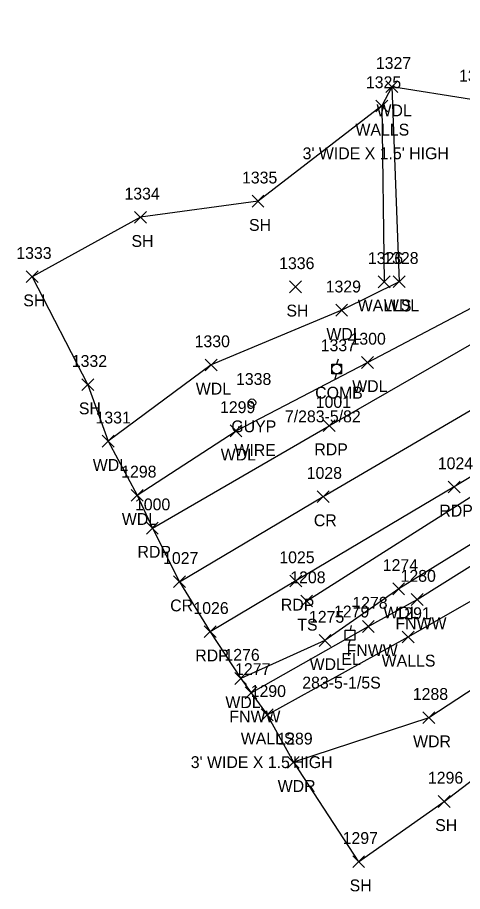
# Model space of a CAD drawing. Extents: x 1526508 to 1531550, y 369926 to 373082.
# Drawn here: x 1530637.1 to 1530712.1, y 369926.2 to 370073.8 of the extents above; entities that cross this region are included whole.
import ezdxf

# ---------------------------------------------------------------- set-up
doc = ezdxf.new("R2010")
doc.units = 0
for name, color, linetype in [('L_A', 7, 'Continuous'), ('L_C', 7, 'Continuous'), ('L_I', 7, 'Continuous'), ('L_TIC', 7, 'Continuous'), ('LAWA', 7, 'Continuous'), ('LELB', 7, 'Continuous'), ('LFNC', 7, 'Continuous'), ('LSOGP', 7, 'Continuous'), ('LWS', 7, 'Continuous'), ('P_A', 7, 'Continuous'), ('P_I', 7, 'Continuous'), ('P_TIC', 7, 'Continuous'), ('PET', 7, 'Continuous'), ('PRC', 7, 'Continuous'), ('U_A', 7, 'Continuous'), ('U_C', 7, 'Continuous'), ('U_I', 7, 'Continuous'), ('UEPT', 7, 'Continuous'), ('UP', 7, 'Continuous'), ('UPGW', 7, 'Continuous')]:
    doc.layers.add(name, color=color, linetype=linetype)

msp = doc.modelspace()

# ---------------------------------------------------------------- linework, layer by layer
at = {"layer": 'L_TIC'}
for points in [[(1530699.23, 370061.11), (1530701.23, 370063.11)], [(1530701.23, 370061.11), (1530699.23, 370063.11)], [(1530697.56, 370057.86), (1530699.56, 370059.86)], [(1530699.56, 370057.86), (1530697.56, 370059.86)], [(1530676.67, 370041.77), (1530678.67, 370043.77)], [(1530678.67, 370041.77), (1530676.67, 370043.77)], [(1530656.84, 370039.06), (1530658.84, 370041.06)], [(1530658.84, 370039.06), (1530656.84, 370041.06)], [(1530638.6, 370029.03), (1530640.6, 370031.03)], [(1530640.6, 370029.03), (1530638.6, 370031.03)], [(1530697.94, 370028.17), (1530699.94, 370030.17)], [(1530699.94, 370028.17), (1530697.94, 370030.17)], [(1530700.48, 370028.19), (1530702.48, 370030.19)], [(1530702.48, 370028.19), (1530700.48, 370030.19)], [(1530682.98, 370027.31), (1530684.98, 370029.31)], [(1530684.98, 370027.31), (1530682.98, 370029.31)], [(1530690.78, 370023.37), (1530692.78, 370025.37)], [(1530692.78, 370023.37), (1530690.78, 370025.37)], [(1530668.76, 370014.13), (1530670.76, 370016.13)], [(1530670.76, 370014.13), (1530668.76, 370016.13)], [(1530695.13, 370014.56), (1530697.13, 370016.56)], [(1530697.13, 370014.56), (1530695.13, 370016.56)], [(1530647.97, 370010.8), (1530649.97, 370012.8)], [(1530649.97, 370010.8), (1530647.97, 370012.8)], [(1530672.96, 370003), (1530674.96, 370005)], [(1530674.96, 370003), (1530672.96, 370005)], [(1530651.4, 370001.25), (1530653.4, 370003.25)], [(1530653.4, 370001.25), (1530651.4, 370003.25)], [(1530656.29, 369992.12), (1530658.29, 369994.12)], [(1530658.29, 369992.12), (1530656.29, 369994.12)], [(1530700.39, 369976.34), (1530702.39, 369978.34)], [(1530702.39, 369976.34), (1530700.39, 369978.34)], [(1530684.88, 369974.28), (1530686.88, 369976.28)], [(1530686.88, 369974.28), (1530684.88, 369976.28)], [(1530703.49, 369974.52), (1530705.49, 369976.52)], [(1530705.49, 369974.52), (1530703.49, 369976.52)], [(1530695.26, 369969.98), (1530697.26, 369971.98)], [(1530697.26, 369969.98), (1530695.26, 369971.98)], [(1530687.96, 369967.61), (1530689.96, 369969.61)], [(1530689.96, 369967.61), (1530687.96, 369969.61)], [(1530701.98, 369968.21), (1530703.98, 369970.21)], [(1530703.98, 369968.21), (1530701.98, 369970.21)], [(1530673.75, 369961.19), (1530675.75, 369963.19)], [(1530675.75, 369961.19), (1530673.75, 369963.19)], [(1530675.49, 369958.78), (1530677.49, 369960.78)], [(1530677.49, 369958.78), (1530675.49, 369960.78)], [(1530678.21, 369955.07), (1530680.21, 369957.07)], [(1530680.21, 369955.07), (1530678.21, 369957.07)], [(1530705.46, 369954.58), (1530707.46, 369956.58)], [(1530707.46, 369954.58), (1530705.46, 369956.58)], [(1530682.63, 369947.04), (1530684.63, 369949.04)], [(1530684.63, 369947.04), (1530682.63, 369949.04)], [(1530708.06, 369940.44), (1530710.06, 369942.44)], [(1530710.06, 369940.44), (1530708.06, 369942.44)], [(1530693.63, 369930.26), (1530695.63, 369932.26)], [(1530695.63, 369930.26), (1530693.63, 369932.26)]]:
    msp.add_lwpolyline(points, dxfattribs=at)
at = {"layer": 'LAWA'}
for points in [[(1530657.29, 369993.12), (1530673.96, 370004), (1530696.13, 370015.56), (1530718.14, 370027.13), (1530730.56, 370035.39), (1530739.6, 370038.43), (1530749.85, 370044.28), (1530746.24, 370053.12), (1530732.92, 370070.22)], [(1530700.23, 370062.11), (1530701.48, 370029.19), (1530691.78, 370024.37), (1530669.76, 370015.13), (1530652.4, 370002.25)], [(1530769.48, 370023.84), (1530754.36, 370014.7), (1530742.13, 370006.46), (1530732.58, 369998.98), (1530723.17, 369990.78), (1530701.39, 369977.34), (1530688.96, 369968.61), (1530674.75, 369962.19)], [(1530749.81, 369965.19), (1530736.04, 369980.46), (1530727.16, 369969.14), (1530706.46, 369955.58), (1530683.63, 369948.04)]]:
    msp.add_lwpolyline(points, dxfattribs=at)
at = {"layer": 'LELB'}
msp.add_lwpolyline([(1530685.88, 369975.28), (1530717.44, 369995.35), (1530750.55, 370015.24), (1530789.81, 370037.94), (1530822.42, 370057.69), (1530849.78, 370074.39), (1530878.97, 370089.95), (1530906.44, 370104.85), (1530934.55, 370113.45), (1530953.41, 370116.76)], dxfattribs=at)
at = {"layer": 'LFNC'}
msp.add_lwpolyline([(1530676.49, 369959.78), (1530696.26, 369970.98), (1530704.49, 369975.52), (1530724.71, 369988.17), (1530736.65, 369993.22), (1530745.64, 369985.38), (1530754.13, 369971.62)], dxfattribs=at)
at = {"layer": 'LSOGP'}
msp.add_lwpolyline([(1530713.68, 370059.96), (1530700.23, 370062.11), (1530698.56, 370058.86), (1530677.67, 370042.77), (1530657.84, 370040.06), (1530639.6, 370030.03), (1530648.97, 370011.8), (1530652.4, 370002.25), (1530657.29, 369993.12), (1530659.86, 369987.59), (1530664.43, 369978.53), (1530669.6, 369970.09), (1530674.75, 369962.19), (1530676.49, 369959.78), (1530679.21, 369956.07), (1530683.63, 369948.04), (1530694.63, 369931.26), (1530709.06, 369941.44), (1530721.94, 369951.28)], dxfattribs=at)
at = {"layer": 'LWS'}
for points in [[(1530698.56, 370058.86), (1530698.94, 370029.17)], [(1530679.21, 369956.07), (1530702.98, 369969.21), (1530717.25, 369977.41), (1530728.07, 369984.76)]]:
    msp.add_lwpolyline(points, dxfattribs=at)
at = {"layer": 'P_TIC'}
for points in [[(1530688.68, 370003.88), (1530690.68, 370005.88)], [(1530690.68, 370003.88), (1530688.68, 370005.88)], [(1530709.76, 369993.53), (1530711.76, 369995.53)], [(1530711.76, 369993.53), (1530709.76, 369995.53)], [(1530687.65, 369991.9), (1530689.65, 369993.9)], [(1530689.65, 369991.9), (1530687.65, 369993.9)], [(1530658.86, 369986.59), (1530660.86, 369988.59)], [(1530660.86, 369986.59), (1530658.86, 369988.59)], [(1530663.43, 369977.53), (1530665.43, 369979.53)], [(1530665.43, 369977.53), (1530663.43, 369979.53)], [(1530683.03, 369977.66), (1530685.03, 369979.66)], [(1530685.03, 369977.66), (1530683.03, 369979.66)], [(1530668.6, 369969.09), (1530670.6, 369971.09)], [(1530670.6, 369969.09), (1530668.6, 369971.09)]]:
    msp.add_lwpolyline(points, dxfattribs=at)
at = {"layer": 'PET'}
for points in [[(1530659.86, 369987.59), (1530689.68, 370004.88), (1530725.77, 370025.63), (1530760.95, 370046.59), (1530789.35, 370063.64), (1530821.52, 370083.59), (1530847.47, 370098.66), (1530877.57, 370115.25), (1530907.84, 370128.26), (1530938.81, 370136.76), (1530967.77, 370140.97), (1531005.44, 370146.08), (1531034.99, 370150.93)], [(1531038.44, 370130.38), (1531006.6, 370125.67), (1530965.47, 370120.56), (1530935.63, 370115.81), (1530906.91, 370106.24), (1530877.46, 370092.89), (1530855.5, 370080.74), (1530824.98, 370062.43), (1530800.48, 370048.15), (1530769.96, 370030.14), (1530741.1, 370012.79), (1530710.76, 369994.53), (1530684.03, 369978.66), (1530669.6, 369970.09)]]:
    msp.add_lwpolyline(points, dxfattribs=at)
at = {"layer": 'PRC'}
msp.add_lwpolyline([(1530664.43, 369978.53), (1530688.65, 369992.9), (1530715.76, 370008.79), (1530744.4, 370025.81), (1530774.39, 370044.32), (1530799.13, 370059.29), (1530828.47, 370076.59), (1530863.72, 370096.73), (1530899.64, 370113.89), (1530935.78, 370125.96), (1530974.77, 370132.27), (1531009.67, 370136.56), (1531036.22, 370140.48)], dxfattribs=at)
at = {"layer": 'UEPT'}
for p, q in [((1530693.35, 369971.16), (1530693.18, 369970.33)), ((1530692.35, 369968.66), (1530692.35, 369970.33)), ((1530692.35, 369970.33), (1530694.01, 369970.33)), ((1530693.18, 369969.5), (1530693.18, 369969.5)), ((1530694.01, 369970.33), (1530694.01, 369968.66)), ((1530694.01, 369968.66), (1530692.35, 369968.66)), ((1530692.93, 369967.83), (1530693.18, 369968.66))]:
    msp.add_line(p, q, dxfattribs=at)
at = {"layer": 'UP'}
for p, q in [((1530690.1, 370013.62), (1530690.1, 370015.28)), ((1530690.1, 370015.28), (1530691.76, 370015.28)), ((1530691.18, 370016.12), (1530690.93, 370015.28)), ((1530691.76, 370015.28), (1530691.76, 370013.62)), ((1530690.93, 370014.45), (1530690.93, 370014.45)), ((1530691.76, 370013.62), (1530690.1, 370013.62)), ((1530690.68, 370012.78), (1530690.93, 370013.62))]:
    msp.add_line(p, q, dxfattribs=at)
msp.add_circle((1530690.93, 370014.45), 0.833, dxfattribs=at)
at = {"layer": 'UPGW'}
for radius in [0.625, 0.0833]:
    msp.add_circle((1530676.65, 370008.76), radius, dxfattribs=at)

# ---------------------------------------------------------------- texts
at = {"layer": 'L_A'}
for s, p in [('WDL', (1530697.65, 370057.11)), ('WALLS', (1530694.1, 370053.86)), ('SH', (1530676.15, 370037.77)), ('SH', (1530656.33, 370035.06)), ('SH', (1530638.09, 370025.03)), ('WALLS', (1530694.48, 370024.17)), ('WDL', (1530698.9, 370024.19)), ('SH', (1530682.46, 370023.31)), ('WDL', (1530689.2, 370019.37)), ('WDL', (1530693.55, 370010.56)), ('WDL', (1530667.18, 370010.13)), ('SH', (1530647.46, 370006.8)), ('WDL', (1530671.38, 369999)), ('WDL', (1530649.81, 369997.25)), ('WDL', (1530654.71, 369988.12)), ('WDL', (1530698.81, 369972.34)), ('FNWW', (1530700.84, 369970.52)), ('TS', (1530684.29, 369970.28)), ('FNWW', (1530692.61, 369965.98)), ('WDL', (1530686.37, 369963.61)), ('WALLS', (1530698.52, 369964.21)), ('WDL', (1530672.17, 369957.19)), ('FNWW', (1530672.84, 369954.78)), ('WALLS', (1530674.76, 369951.07)), ('WDR', (1530703.82, 369950.58)), ('WDR', (1530680.99, 369943.04)), ('SH', (1530707.55, 369936.44)), ('SH', (1530693.12, 369926.26))]:
    msp.add_text(s, height=2, dxfattribs=at).set_placement(p)
at = {"layer": 'L_C'}
for s, p in [("3' WIDE X 1.5' HIGH", (1530685.19, 370049.86)), ("3' WIDE X 1.5'HIGH", (1530666.33, 369947.07))]:
    msp.add_text(s, height=2, dxfattribs=at).set_placement(p)
at = {"layer": 'L_I'}
for s, p in [('1327', (1530697.54, 370065.11)), ('1325', (1530695.86, 370061.86)), ('1321', (1530711.56, 370062.96)), ('1335', (1530674.97, 370045.77)), ('1334', (1530655.15, 370043.06)), ('1333', (1530636.91, 370033.03)), ('1336', (1530681.23, 370031.31)), ('1326', (1530696.19, 370032.17)), ('1328', (1530698.79, 370032.19)), ('1329', (1530689.08, 370027.37)), ('1330', (1530666.98, 370018.13)), ('1300', (1530693.27, 370018.56)), ('1332', (1530646.27, 370014.8)), ('1299', (1530671.26, 370007)), ('1331', (1530650.27, 370005.25)), ('1298', (1530654.6, 369996.12)), ('1274', (1530698.7, 369980.34)), ('1208', (1530683.11, 369978.28)), ('1280', (1530701.71, 369978.52)), ('1278', (1530693.57, 369973.98)), ('1291', (1530700.85, 369972.21)), ('1275', (1530686.26, 369971.61)), ('1276', (1530672, 369965.19)), ('1277', (1530673.8, 369962.78)), ('1290', (1530676.43, 369959.07)), ('1288', (1530703.77, 369958.58)), ('1289', (1530680.93, 369951.04)), ('1296', (1530706.32, 369944.44)), ('1297', (1530691.94, 369934.26))]:
    msp.add_text(s, height=2, dxfattribs=at).set_placement(p)
at = {"layer": 'P_A'}
for s, p in [('RDP', (1530687.17, 369999.88)), ('RDP', (1530708.25, 369989.53)), ('CR', (1530687.08, 369987.9)), ('RDP', (1530657.35, 369982.59)), ('CR', (1530662.86, 369973.53)), ('RDP', (1530681.52, 369973.66)), ('RDP', (1530667.09, 369965.09))]:
    msp.add_text(s, height=2, dxfattribs=at).set_placement(p)
at = {"layer": 'P_I'}
for s, p in [('1001', (1530687.4, 370007.88)), ('1024', (1530707.99, 369997.53)), ('1028', (1530685.88, 369995.9)), ('1000', (1530656.92, 369990.59)), ('1027', (1530661.66, 369981.53)), ('1025', (1530681.26, 369981.66)), ('1026', (1530666.77, 369973.09))]:
    msp.add_text(s, height=2, dxfattribs=at).set_placement(p)
at = {"layer": 'U_A'}
for s, p in [('COMB', (1530687.31, 370009.45)), ('GUYP', (1530673.17, 370003.76)), ('EL', (1530691.72, 369964.5))]:
    msp.add_text(s, height=2, dxfattribs=at).set_placement(p)
at = {"layer": 'U_C'}
for s, p in [('7/283-5/82', (1530682.2, 370005.45)), ('WIRE', (1530673.69, 369999.76)), ('283-5-1/5S', (1530685.13, 369960.5))]:
    msp.add_text(s, height=2, dxfattribs=at).set_placement(p)
at = {"layer": 'U_I'}
for s, p in [('1337', (1530688.24, 370017.45)), ('1338', (1530673.96, 370011.76)), ('1279', (1530690.48, 369972.5))]:
    msp.add_text(s, height=2, dxfattribs=at).set_placement(p)

doc.saveas('drawing.dxf')
